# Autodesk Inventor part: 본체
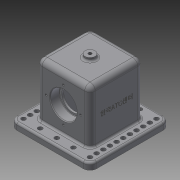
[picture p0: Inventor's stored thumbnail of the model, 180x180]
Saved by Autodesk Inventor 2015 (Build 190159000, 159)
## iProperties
Created: 2018-11
Part Number: 본체
Material: 일반
Document SubType Name: Modeling
Designer: now
Density: 1 g/cm^3
Appearance: 기본값
Author: now
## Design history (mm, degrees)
sketch "스케치1"
  geometry: L1 (-60, 60)-(60, 60); L2 (60, 60)-(60, -60); L3 (60, -60)-(-60, -60); L4 (-60, -60)-(-60, 60); L5 (-60, 60)-(60, -60); L6 (60, 60)-(-60, -60); 1 further point
  constraints: 12 end point, 2 midpoint, 2 parallel, 1 horizontal, 1 perpendicular
  dimensions: "d0" = 120 distance of L1.start L1.end; "d1" = 120 distance of L3.end L1.start
extrude "돌출1" new body sketch "스케치1" distance "d2" = 10; taper "d3" = 0 deg
sketch "스케치2"
  geometry: L1 (-40, 40)-(40, 40); L2 (40, 40)-(40, -40); L3 (40, -40)-(-40, -40); L4 (-40, -40)-(-40, 40); L5 (-40, 40)-(40, -40); L6 (40, 40)-(-40, -40); 1 further point
  constraints: 12 end point, 2 midpoint, 2 parallel, 1 horizontal, 1 perpendicular
  dimensions: "d4" = 80 distance of L1.start L1.end; "d5" = 80 distance of L3.end L1.start
extrude "돌출2" join sketch "스케치2" distance "d6" = 80; taper "d7" = 0 deg
sketch "스케치3"
  geometry: L1 (-30, -23)-(30, -23); L2 (30, -23)-(30, 23); L3 (30, 23)-(-30, 23); L4 (-30, 23)-(-30, -23); L5 (-30, -23)-(30, 23); L6 (30, -23)-(-30, 23); 1 further point
  constraints: 12 end point, 2 midpoint, 2 parallel, 1 horizontal, 1 perpendicular
  dimensions: "d8" = 46 distance of L3.end L1.start; "d9" = 60 distance of L1.start L1.end
extrude "돌출3" cut sketch "스케치3" distance "d10" = 80; taper "d11" = 0 deg
sketch "스케치4"
  geometry: L1 (-20, -10)-(-20, 0) reference; L2 (-20, 0)-(0, 0) reference; L3 (0, 0)-(0, 80) reference; L4 (0, 80)-(80, 80) reference; L5 (80, 80)-(80, 0) reference; L6 (80, 0)-(100, 0) reference; L7 (100, 0)-(100, -10) reference; L8 (100, -10)-(-20, -10) reference; L9 (0, 0)-(80, 0) reference; C1 r 20 at (40, 38); 2 further points
  constraints: 1 centre point, 1 midpoint, 1 vertical alignment
  dimensions: "d12" = 40 diameter of C1; "d13" = 48 distance from line of L8 C1.centre
extrude "돌출4" cut sketch "스케치4" distance "d14" = 14; taper "d15" = 0 deg
sketch "스케치5"
  geometry: C1 r 20 at (0, 0) reference; C2 r 16.5 at (0, 0); 1 further point
  constraints: 1 centre point, 1 coincident
  dimensions: "d16" = 33 diameter of C2
extrude "돌출5" cut sketch "스케치5" distance "d17" = 3; taper "d18" = 0 deg
sketch "스케치6"
  geometry: L1 (-20, -10)-(-20, 0) reference; L2 (-20, 0)-(0, 0) reference; L3 (0, 0)-(0, 80) reference; L4 (0, 80)-(80, 80) reference; L5 (80, 80)-(80, 0) reference; L6 (80, 0)-(100, 0) reference; L7 (100, 0)-(100, -10) reference; L8 (100, -10)-(-20, -10) reference; L9 (0, 0)-(80, 0) reference; C1 r 20 at (40, 38) reference; C2 r 20 at (40, 38) reference; 2 further points
  constraints: 1 vertical alignment
  dimensions: "d19" = 26 distance of C1.centre point (40, 64)
hole "구멍1" sketch "스케치6" at (40, 64) diameter "d20" = 3.242; stored, may be unused: countersink angle "d24" = 90 deg, drill point angle "d26" = 118 deg; dims "d21" = 8, "d22" = 4, "d23" = 2, "d25" = 10
node "작업 평면1"
sketch "스케치7"
  geometry: C1 r 7.5 at (0, 0); 1 further point
  constraints: 1 centre point, 1 coincident
  dimensions: "d31" = 15 diameter of C1
extrude "돌출6" join sketch "스케치7" stored distance "d32" = 0; taper "d33" = 0 deg
sketch "스케치8"
  geometry: C1 r 7.5 at (0, 0) reference
hole "구멍2" sketch "스케치8" at (0, 0) diameter "d34" = 4.917; stored, may be unused: countersink angle "d38" = 90 deg, drill point angle "d40" = 0 deg; dims "d35" = 12, "d36" = 4, "d37" = 2, "d39" = 30
node "작업 평면2"
sketch "스케치10"
  geometry: L1 (60, 0)-(-60, 0) reference; 3 further points
  constraints: 1 midpoint, 1 vertical alignment, 1 other
  dimensions: "d42" = 48 distance from line of L1 point (0, 48)
feature "엠보싱1" sketch "스케치10" dims "d0" = 120, "d1" = 120, "d8" = 46, "d9" = 60, "d43" = 0.5, "d44" = 0
fillet "모깎기1" dims "d45" = 10
sketch "스케치12"
  geometry: A1 r 10 centre (50, -50) between (50, -60) and (60, -50) reference; 1 further point
hole "구멍3" sketch "스케치12" at (50, -50) diameter "d46" = 6.6; stored, may be unused: countersink angle "d50" = 90 deg, drill point angle "d52" = 0 deg; dims "d47" = 12, "d48" = 4, "d49" = 2, "d51" = 30
fillet "모깎기2" dims "d59" = 3
fillet "모깎기3" dims "d60" = 8
fillet "모깎기4" dims "d61" = 8
chamfer "모따기1" distance "d62" = 1; stored, may be unused: second distance "d63" = 2, angle "d64" = 45 deg
fillet "모깎기5" dims "d65" = 0.6
fillet "모깎기6" dims "d66" = 3
fillet "모깎기7" dims "d67" = 3
fillet "모깎기8" dims "d68" = 3
node "솔리드1"
pattern_circular "원형 패턴1" dims angle "d28" = 360 deg
mirror "대칭1"
mirror "대칭2"
pattern_linear "직사각형 패턴1" dims "d55" = 10
pattern_linear "직사각형 패턴2" dims "d58" = 25
mirror "대칭3"
mirror "대칭4"
node "절단 모서리 투영1"
node "절단 모서리 투영2"
other parameters: "d30" = 95, "d41" = 58
